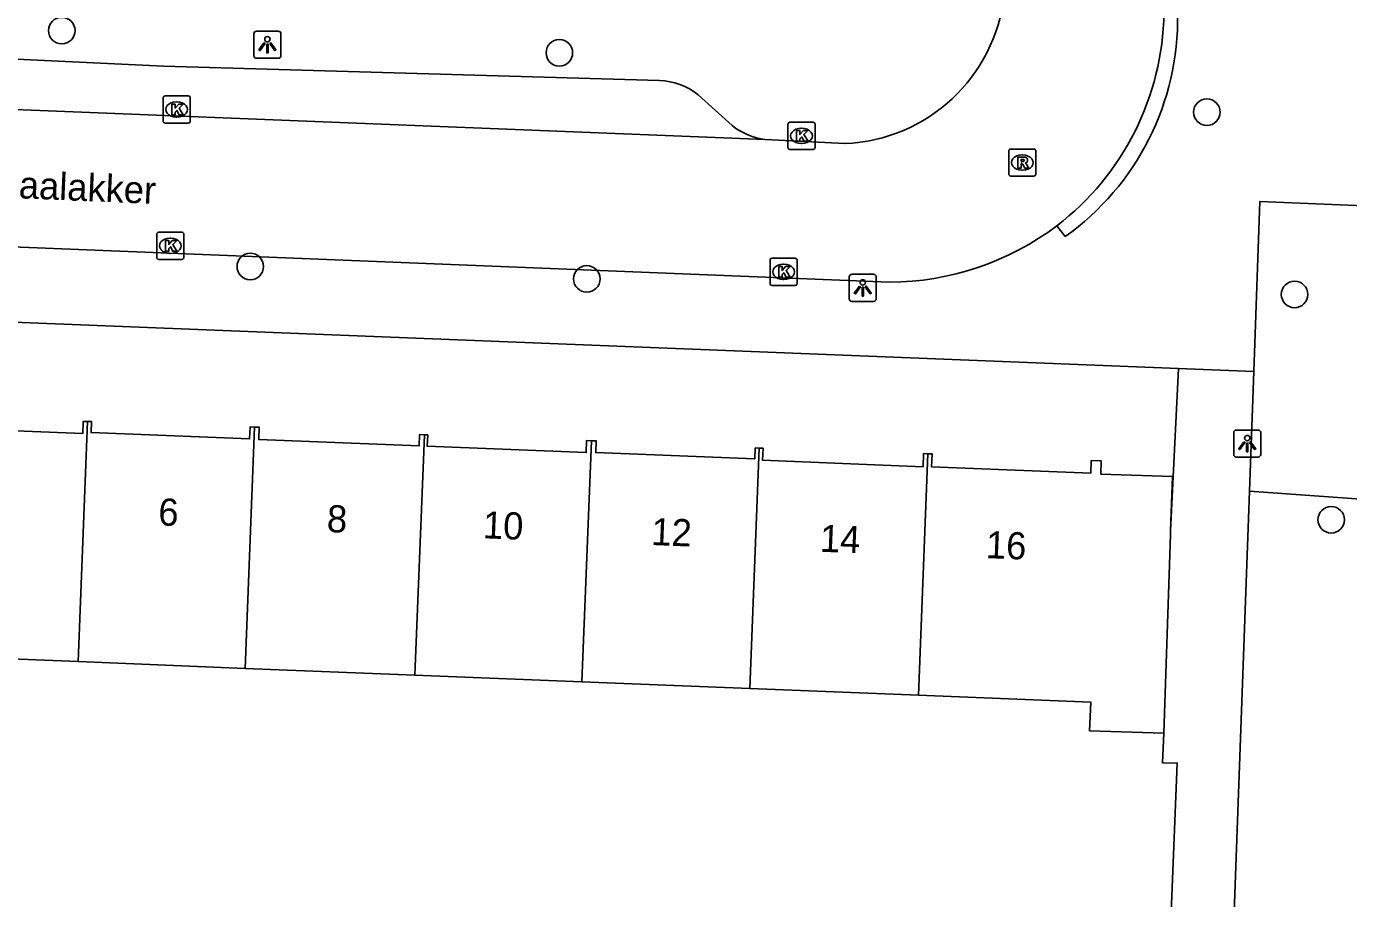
# Model space of a CAD drawing. Extents: x 161355 to 162026, y 386504 to 387459.
# Drawn here: x 161829.52 to 161878.24, y 386785.22 to 386817.34 of the extents above; entities that cross this region are included whole.
import ezdxf

# ---------------------------------------------------------------- set-up
doc = ezdxf.new("R2010")
doc.units = 0
for name, color, linetype in [('IMGEO_Boom', 7, 'Continuous'), ('IMGEO_Groenvoorziening', 7, 'Continuous'), ('IMGEO_Kolk', 7, 'Continuous'), ('IMGEO_Lichtpunt', 7, 'Continuous'), ('IMGEO_Openbare_ruimte_label', 7, 'Continuous'), ('IMGEO_Pand', 7, 'Continuous'), ('IMGEO_Pand_nummerreeks', 7, 'Continuous'), ('IMGEO_Rijbaan_lokaal_open', 7, 'Continuous'), ('IMGEO_Rioolput', 7, 'Continuous'), ('IMGEO_Voetpad_open', 7, 'Continuous')]:
    doc.layers.add(name, color=color, linetype=linetype)

msp = doc.modelspace()

# ---------------------------------------------------------------- linework, layer by layer
at = {"layer": 'IMGEO_Boom'}
for centre in [(161830.824, 386817.188), (161849.159, 386816.372), (161873.02, 386814.186), (161837.772, 386808.5), (161850.172, 386808.043), (161876.252, 386807.472), (161877.602, 386799.172)]:
    msp.add_circle(centre, 0.489, dxfattribs=at)
at = {"layer": 'IMGEO_Groenvoorziening'}
msp.add_lwpolyline([(161874.587, 386800.222), (161879.556, 386799.87)], dxfattribs=at)
at = {"layer": 'IMGEO_Kolk'}
for p, q in [((161834.559, 386813.858), (161834.559, 386814.71)), ((161834.634, 386814.784), (161835.486, 386814.784)), ((161835.047, 386814.564), (161835.072, 386814.564)), ((161835.56, 386814.71), (161835.56, 386813.858)), ((161835.07, 386814.004), (161835.045, 386814.004)), ((161835.486, 386813.784), (161834.634, 386813.784)), ((161857.581, 386812.886), (161857.581, 386813.738)), ((161857.656, 386813.812), (161858.508, 386813.812)), ((161858.069, 386813.592), (161858.094, 386813.592)), ((161858.582, 386813.738), (161858.582, 386812.886)), ((161858.092, 386813.032), (161858.067, 386813.032)), ((161858.508, 386812.812), (161857.656, 386812.812)), ((161834.324, 386808.838), (161834.324, 386809.69)), ((161834.399, 386809.764), (161835.251, 386809.764)), ((161834.812, 386809.544), (161834.837, 386809.544)), ((161835.325, 386809.69), (161835.325, 386808.838)), ((161835.251, 386808.764), (161834.399, 386808.764)), ((161834.835, 386808.984), (161834.81, 386808.984)), ((161856.923, 386807.878), (161856.923, 386808.73)), ((161856.998, 386808.804), (161857.85, 386808.804)), ((161857.411, 386808.584), (161857.436, 386808.584)), ((161857.924, 386808.73), (161857.924, 386807.878)), ((161857.85, 386807.804), (161856.998, 386807.804)), ((161857.434, 386808.024), (161857.409, 386808.024))]:
    msp.add_line(p, q, dxfattribs=at)
for points in [[(161834.559, 386813.858), (161834.559, 386814.71)], [(161834.634, 386814.784), (161835.486, 386814.784)], [(161834.88, 386814.484), (161835.003, 386814.484), (161835.003, 386814.333), (161835.133, 386814.484), (161835.297, 386814.484), (161835.151, 386814.333), (161835.304, 386814.084), (161835.152, 386814.084), (161835.067, 386814.248), (161835.003, 386814.181), (161835.003, 386814.084), (161834.88, 386814.084), (161834.88, 386814.484)], [(161835.56, 386814.71), (161835.56, 386813.858)], [(161835.486, 386813.784), (161834.634, 386813.784)], [(161857.581, 386812.886), (161857.581, 386813.738)], [(161857.656, 386813.812), (161858.508, 386813.812)], [(161857.902, 386813.512), (161858.025, 386813.512), (161858.025, 386813.361), (161858.155, 386813.512), (161858.319, 386813.512), (161858.173, 386813.361), (161858.326, 386813.112), (161858.174, 386813.112), (161858.089, 386813.276), (161858.025, 386813.209), (161858.025, 386813.112), (161857.902, 386813.112), (161857.902, 386813.512)], [(161858.582, 386813.738), (161858.582, 386812.886)], [(161858.508, 386812.812), (161857.656, 386812.812)], [(161834.324, 386808.838), (161834.324, 386809.69)], [(161834.399, 386809.764), (161835.251, 386809.764)], [(161835.325, 386809.69), (161835.325, 386808.838)], [(161834.645, 386809.464), (161834.768, 386809.464), (161834.768, 386809.313), (161834.898, 386809.464), (161835.062, 386809.464), (161834.916, 386809.313), (161835.069, 386809.064), (161834.917, 386809.064), (161834.832, 386809.228), (161834.768, 386809.161), (161834.768, 386809.064), (161834.645, 386809.064), (161834.645, 386809.464)], [(161835.251, 386808.764), (161834.399, 386808.764)], [(161856.923, 386807.878), (161856.923, 386808.73)], [(161856.998, 386808.804), (161857.85, 386808.804)], [(161857.924, 386808.73), (161857.924, 386807.878)], [(161857.244, 386808.504), (161857.367, 386808.504), (161857.367, 386808.353), (161857.497, 386808.504), (161857.661, 386808.504), (161857.515, 386808.353), (161857.668, 386808.104), (161857.516, 386808.104), (161857.431, 386808.268), (161857.367, 386808.201), (161857.367, 386808.104), (161857.244, 386808.104), (161857.244, 386808.504)], [(161857.85, 386807.804), (161856.998, 386807.804)]]:
    msp.add_lwpolyline(points, dxfattribs=at)
for centre, start, end in [((161834.636, 386814.708), 91.552, 178.448), ((161834.636, 386814.708), 91.552, 178.448), ((161835.484, 386814.708), 1.552, 88.448), ((161835.484, 386814.708), 1.552, 88.448), ((161834.636, 386813.86), 181.552, 268.448), ((161834.636, 386813.86), 181.552, 268.448), ((161835.484, 386813.86), 271.552, 358.448), ((161835.484, 386813.86), 271.552, 358.448), ((161857.658, 386813.736), 91.552, 178.448), ((161857.658, 386813.736), 91.552, 178.448), ((161858.506, 386813.736), 1.552, 88.448), ((161858.506, 386813.736), 1.552, 88.448), ((161857.658, 386812.888), 181.552, 268.448), ((161857.658, 386812.888), 181.552, 268.448), ((161858.506, 386812.888), 271.552, 358.448), ((161858.506, 386812.888), 271.552, 358.448), ((161834.401, 386809.688), 91.552, 178.448), ((161834.401, 386809.688), 91.552, 178.448), ((161835.249, 386809.688), 1.552, 88.448), ((161835.249, 386809.688), 1.552, 88.448), ((161834.401, 386808.84), 181.552, 268.448), ((161834.401, 386808.84), 181.552, 268.448), ((161835.249, 386808.84), 271.552, 358.448), ((161835.249, 386808.84), 271.552, 358.448), ((161857, 386808.728), 91.552, 178.448), ((161857, 386808.728), 91.552, 178.448), ((161857.848, 386808.728), 1.552, 88.448), ((161857.848, 386808.728), 1.552, 88.448), ((161857, 386807.88), 181.552, 268.448), ((161857, 386807.88), 181.552, 268.448), ((161857.848, 386807.88), 271.552, 358.448), ((161857.848, 386807.88), 271.552, 358.448)]:
    msp.add_arc(centre, 0.0765, start, end, dxfattribs=at)
for centre, major_axis, ratio, start_param, end_param in [((161835.046, 386814.284), (-0.387, 0.002), 0.722429, 4.712389, 7.853982), ((161835.071, 386814.284), (-0.39, 0.002), 0.717154, 1.570796, 4.712389), ((161858.068, 386813.312), (-0.387, 0.002), 0.722429, 4.712389, 7.853982), ((161858.093, 386813.312), (-0.39, 0.002), 0.717154, 1.570796, 4.712389), ((161834.811, 386809.264), (-0.387, 0.002), 0.722429, 4.712389, 7.853982), ((161834.836, 386809.264), (-0.39, 0.002), 0.717154, 1.570796, 4.712389), ((161857.41, 386808.304), (-0.387, 0.002), 0.722429, 4.712389, 7.853982), ((161857.435, 386808.304), (-0.39, 0.002), 0.717154, 1.570796, 4.712389)]:
    msp.add_ellipse(centre, major_axis=major_axis, ratio=ratio, start_param=start_param, end_param=end_param, dxfattribs=at)
at = {"layer": 'IMGEO_Lichtpunt'}
for p, q in [((161837.902, 386817.074), (161837.902, 386816.267)), ((161837.902, 386817.074), (161837.902, 386816.267)), ((161838.804, 386817.169), (161837.996, 386817.169)), ((161838.804, 386817.169), (161837.996, 386817.169)), ((161838.898, 386816.267), (161838.898, 386817.074)), ((161838.898, 386816.267), (161838.898, 386817.074)), ((161837.996, 386816.173), (161838.804, 386816.173)), ((161837.996, 386816.173), (161838.804, 386816.173)), ((161859.842, 386808.117), (161859.842, 386807.31)), ((161859.842, 386808.117), (161859.842, 386807.31)), ((161860.744, 386808.212), (161859.936, 386808.212)), ((161860.744, 386808.212), (161859.936, 386808.212)), ((161860.838, 386807.31), (161860.838, 386808.117)), ((161860.838, 386807.31), (161860.838, 386808.117)), ((161859.936, 386807.216), (161860.744, 386807.216)), ((161859.936, 386807.216), (161860.744, 386807.216)), ((161874.008, 386802.382), (161874.008, 386801.575)), ((161874.008, 386802.382), (161874.008, 386801.575)), ((161874.91, 386802.477), (161874.102, 386802.477)), ((161874.91, 386802.477), (161874.102, 386802.477)), ((161875.004, 386801.575), (161875.004, 386802.382)), ((161875.004, 386801.575), (161875.004, 386802.382)), ((161874.102, 386801.481), (161874.91, 386801.481)), ((161874.102, 386801.481), (161874.91, 386801.481))]:
    msp.add_line(p, q, dxfattribs=at)
for points in [[(161838.276, 386816.738), (161838.315, 386816.71), (161838.127, 386816.448), (161838.089, 386816.475), (161838.276, 386816.738)], [(161838.378, 386816.69), (161838.425, 386816.69), (161838.425, 386816.368), (161838.378, 386816.368), (161838.378, 386816.69)], [(161838.488, 386816.71), (161838.526, 386816.737), (161838.713, 386816.475), (161838.674, 386816.447), (161838.488, 386816.71)], [(161860.216, 386807.781), (161860.255, 386807.753), (161860.067, 386807.491), (161860.029, 386807.518), (161860.216, 386807.781)], [(161860.318, 386807.733), (161860.365, 386807.733), (161860.365, 386807.411), (161860.318, 386807.411), (161860.318, 386807.733)], [(161860.428, 386807.753), (161860.466, 386807.78), (161860.653, 386807.518), (161860.614, 386807.49), (161860.428, 386807.753)], [(161874.382, 386802.046), (161874.421, 386802.018), (161874.233, 386801.756), (161874.195, 386801.783), (161874.382, 386802.046)], [(161874.484, 386801.998), (161874.531, 386801.998), (161874.531, 386801.676), (161874.484, 386801.676), (161874.484, 386801.998)], [(161874.594, 386802.018), (161874.632, 386802.045), (161874.819, 386801.783), (161874.78, 386801.755), (161874.594, 386802.018)]]:
    msp.add_lwpolyline(points, dxfattribs=at)
for centre in [(161838.401, 386816.872), (161860.341, 386807.915), (161874.507, 386802.18)]:
    msp.add_circle(centre, 0.0994, dxfattribs=at)
for centre, start, end in [((161837.996, 386817.074), 90, 180), ((161837.996, 386817.074), 90, 180), ((161838.804, 386817.074), 0, 90), ((161838.804, 386817.074), 0, 90), ((161837.996, 386816.267), 180, 270), ((161837.996, 386816.267), 180, 270), ((161838.804, 386816.267), 270, 0), ((161838.804, 386816.267), 270, 360), ((161859.936, 386808.117), 90, 180), ((161859.936, 386808.117), 90, 180), ((161860.744, 386808.117), 0, 90), ((161860.744, 386808.117), 0, 90), ((161859.936, 386807.31), 180, 270), ((161859.936, 386807.31), 180, 270), ((161860.744, 386807.31), 270, 0), ((161860.744, 386807.31), 270, 360), ((161874.102, 386802.382), 90, 180), ((161874.102, 386802.382), 90, 180), ((161874.91, 386802.382), 0, 90), ((161874.91, 386802.382), 0, 90), ((161874.102, 386801.575), 180, 270), ((161874.102, 386801.575), 180, 270), ((161874.91, 386801.575), 270, 0), ((161874.91, 386801.575), 270, 360)]:
    msp.add_arc(centre, 0.0946, start, end, dxfattribs=at)
at = {"layer": 'IMGEO_Pand'}
for points in [[(161831.768, 386802.791), (161831.617, 386802.797), (161831.6, 386802.353), (161825.709, 386802.588), (161825.727, 386803.04), (161825.57, 386803.047)], [(161831.768, 386802.791), (161831.423, 386793.945)], [(161837.932, 386802.584), (161837.763, 386802.591), (161837.745, 386802.148), (161831.905, 386802.381), (161831.921, 386802.785), (161831.768, 386802.791)], [(161837.932, 386802.584), (161837.586, 386793.698)], [(161844.185, 386802.302), (161844.01, 386802.309), (161843.993, 386801.891), (161838.081, 386802.127), (161838.099, 386802.578), (161837.932, 386802.584)], [(161843.839, 386793.448), (161844.185, 386802.302)], [(161850.34, 386802.082), (161850.166, 386802.089), (161850.149, 386801.647), (161844.294, 386801.881), (161844.31, 386802.297), (161844.185, 386802.302)], [(161849.993, 386793.202), (161850.34, 386802.082)], [(161856.52, 386801.81), (161856.376, 386801.816), (161856.36, 386801.41), (161850.5, 386801.644), (161850.517, 386802.075), (161850.34, 386802.082)], [(161856.52, 386801.81), (161856.175, 386792.955)], [(161862.735, 386801.603), (161862.582, 386801.609), (161862.563, 386801.126), (161856.649, 386801.362), (161856.667, 386801.804), (161856.52, 386801.81)], [(161862.388, 386792.707), (161862.735, 386801.603)], [(161871.684, 386798.765), (161871.753, 386800.766), (161869.111, 386800.856), (161869.13, 386801.337), (161868.758, 386801.352), (161868.739, 386800.889), (161862.872, 386801.123), (161862.891, 386801.597), (161862.735, 386801.603)], [(161871.684, 386798.765), (161871.679, 386798.614), (161871.431, 386791.311)], [(161831.423, 386793.945), (161825.224, 386794.192)], [(161837.586, 386793.698), (161831.423, 386793.945)], [(161843.839, 386793.448), (161837.586, 386793.698)], [(161849.993, 386793.202), (161843.839, 386793.448)], [(161856.175, 386792.955), (161849.993, 386793.202)], [(161862.388, 386792.707), (161856.175, 386792.955)], [(161871.431, 386791.311), (161868.697, 386791.399), (161868.739, 386792.453), (161862.388, 386792.707)]]:
    msp.add_lwpolyline(points, dxfattribs=at)
at = {"layer": 'IMGEO_Rijbaan_lokaal_open'}
for points in [[(161856.748, 386813.177), (161812.486, 386814.946)], [(161856.748, 386813.177), (161859.685, 386813.028)], [(161861.323, 386807.92), (161808.25, 386810.055)]]:
    msp.add_lwpolyline(points, dxfattribs=at)
for centre, radius, start, end in [((161859.433, 386819.174), 6.151, 272.3507, 353.7392), ((161861.33, 386818.018), 10.113, 307.5437, 358.9641), ((161861.26, 386818.303), 10.383, 270.3489, 306.8939)]:
    msp.add_arc(centre, radius, start, end, dxfattribs=at)
at = {"layer": 'IMGEO_Rioolput'}
for p, q in [((161865.718, 386811.902), (161865.718, 386812.754)), ((161865.793, 386812.828), (161866.645, 386812.828)), ((161866.206, 386812.608), (161866.231, 386812.608)), ((161866.719, 386812.754), (161866.719, 386811.902)), ((161866.229, 386812.048), (161866.204, 386812.048)), ((161866.645, 386811.828), (161865.793, 386811.828))]:
    msp.add_line(p, q, dxfattribs=at)
for points in [[(161865.718, 386811.902), (161865.718, 386812.754)], [(161865.793, 386812.828), (161866.645, 386812.828)], [(161866.307, 386812.526), (161866.055, 386812.528), (161866.055, 386812.128)], [(161866.233, 386812.447), (161866.179, 386812.447), (161866.179, 386812.366)], [(161866.719, 386812.754), (161866.719, 386811.902)], [(161866.055, 386812.128), (161866.179, 386812.128), (161866.179, 386812.29), (161866.19, 386812.29)], [(161866.179, 386812.366), (161866.231, 386812.366)], [(161866.237, 386812.261), (161866.308, 386812.128), (161866.448, 386812.128), (161866.383, 386812.254)], [(161866.645, 386811.828), (161865.793, 386811.828)]]:
    msp.add_lwpolyline(points, dxfattribs=at)
for centre, radius, start, end in [((161865.795, 386812.752), 0.0765, 91.552, 178.448), ((161865.795, 386812.752), 0.0765, 91.552, 178.448), ((161866.239, 386812.351), 0.0964, 77.0061, 93.1865), ((161866.253, 386812.408), 0.0378, 276.6634, 79.6772), ((161866.306, 386812.416), 0.109, 350.3612, 89.416), ((161866.643, 386812.752), 0.0765, 1.552, 88.448), ((161866.643, 386812.752), 0.0765, 1.552, 88.448), ((161866.189, 386812.237), 0.0533, 26.0293, 88.6989), ((161866.215, 386812.555), 0.19, 274.7715, 282.9687), ((161866.304, 386812.416), 0.112, 277.5842, 350.9817), ((161866.288, 386812.201), 0.108, 29.5134, 73.7905), ((161865.795, 386811.904), 0.0765, 181.552, 268.448), ((161865.795, 386811.904), 0.0765, 181.552, 268.448), ((161866.643, 386811.904), 0.0765, 271.552, 358.448), ((161866.643, 386811.904), 0.0765, 271.552, 358.448)]:
    msp.add_arc(centre, radius, start, end, dxfattribs=at)
for centre, major_axis, ratio, start_param, end_param in [((161866.205, 386812.328), (-0.387, 0.002), 0.722429, 4.712389, 7.853982), ((161866.23, 386812.328), (-0.39, 0.002), 0.717154, 1.570796, 4.712389)]:
    msp.add_ellipse(centre, major_axis=major_axis, ratio=ratio, start_param=start_param, end_param=end_param, dxfattribs=at)
at = {"layer": 'IMGEO_Voetpad_open'}
for points in [[(161816.522, 386816.734), (161834.57, 386815.884), (161852.847, 386815.353)], [(161854.28, 386814.826), (161855.528, 386813.688)], [(161874.747, 386804.628), (161874.974, 386810.898), (161880.002, 386810.68)], [(161867.794, 386809.6), (161867.493, 386809.999)], [(161807.869, 386805.505), (161807.933, 386805.701), (161808.014, 386805.891), (161808.111, 386806.073), (161808.225, 386806.246), (161808.353, 386806.408), (161808.496, 386806.557), (161808.651, 386806.694), (161808.817, 386806.816), (161808.994, 386806.922), (161809.18, 386807.012), (161809.373, 386807.086), (161809.572, 386807.142), (161809.775, 386807.179), (161809.981, 386807.199), (161810.187, 386807.2), (161871.979, 386804.738)], [(161871.979, 386804.738), (161871.684, 386798.765)], [(161871.979, 386804.738), (161874.747, 386804.628)], [(161874.587, 386800.222), (161874.747, 386804.628)], [(161873.877, 386780.663), (161874.587, 386800.222)], [(161871.431, 386791.311), (161871.381, 386790.22), (161871.928, 386790.211), (161871.542, 386780.734), (161871.106, 386770.041), (161870.503, 386770.041), (161870.449, 386768.915)]]:
    msp.add_lwpolyline(points, dxfattribs=at)
for centre, radius, start, end in [((161862.079, 386817.64), 9.865, 305.4061, 0.9846), ((161852.745, 386812.865), 2.49, 51.9554, 87.6616), ((161857.054, 386815.619), 2.461, 231.6828, 262.8642)]:
    msp.add_arc(centre, radius, start, end, dxfattribs=at)

# ---------------------------------------------------------------- texts
at = {"layer": 'IMGEO_Openbare_ruimte_label'}
msp.add_text('Maalakker', height=1, rotation=357.5926, dxfattribs=at).set_placement((161828.116, 386811.062))
at = {"layer": 'IMGEO_Pand_nummerreeks'}
for s, rotation, p in [('6', 357.7135, (161834.367, 386798.969)), ('8', 357.7135, (161840.58, 386798.721)), ('10', 357.7135, (161846.329, 386798.491)), ('12', 357.7135, (161852.533, 386798.243)), ('14', 357.7135, (161858.746, 386797.995)), ('16', 357.716, (161864.862, 386797.76))]:
    msp.add_text(s, height=1, rotation=rotation, dxfattribs=at).set_placement(p)

doc.saveas('drawing.dxf')
